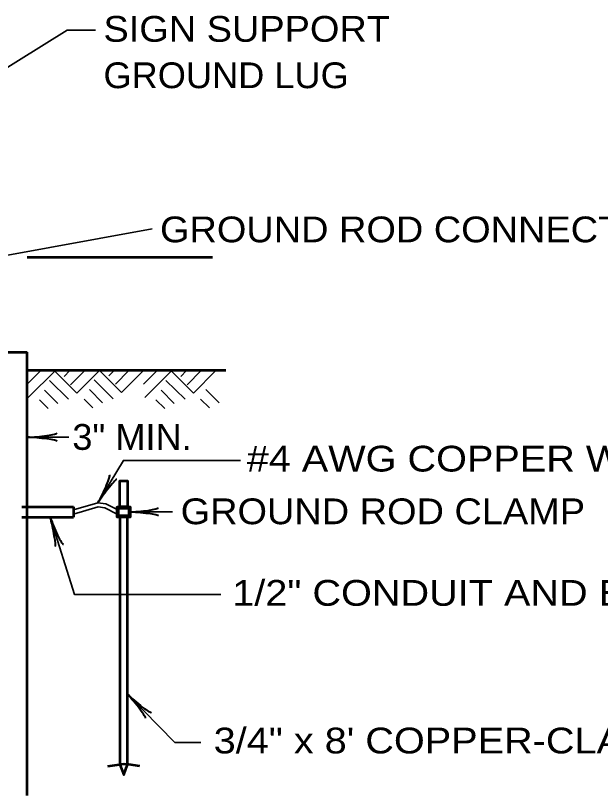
# Model space of a CAD drawing. Extents: x -68 to 612, y -58 to 382.
# Drawn here: x 208.3 to 265, y 135 to 210.6 of the extents above; entities that cross this region are included whole.
import ezdxf

# ---------------------------------------------------------------- set-up
doc = ezdxf.new("R2010")
doc.units = 0
doc.linetypes.add('LONG_DASHED', pattern=[7.5, 6, -1.5])
doc.layers.add('1', color=7, linetype='Continuous', lineweight=53)

msp = doc.modelspace()

# ---------------------------------------------------------------- linework, layer by layer
at = {"layer": '1', "lineweight": 35}
for p, q in [((195.016, 185.14), (221.485, 189.97)), ((210.686, 176.235), (209.366, 174.915)), ((212.106, 176.235), (209.486, 173.615)), ((212.006, 176.235), (214.206, 174.035)), ((213.526, 176.235), (212.966, 175.655)), ((214.966, 176.235), (213.586, 174.855)), ((216.386, 176.235), (214.206, 174.035)), ((216.386, 176.235), (218.526, 174.095)), ((217.806, 176.235), (217.286, 175.715)), ((219.246, 176.235), (217.926, 174.915)), ((220.666, 176.235), (218.526, 174.095)), ((221.986, 176.235), (220.666, 174.915)), ((223.406, 176.235), (220.786, 173.615)), ((223.306, 176.235), (225.506, 174.035)), ((224.826, 176.235), (224.266, 175.655)), ((226.266, 176.235), (224.886, 174.855)), ((227.686, 176.235), (225.506, 174.035)), ((211.526, 175.275), (213.386, 173.435)), ((215.866, 175.335), (217.706, 173.495)), ((222.826, 175.275), (224.686, 173.435)), ((211.066, 174.315), (212.346, 173.035)), ((215.406, 174.375), (216.686, 173.095)), ((222.366, 174.315), (223.646, 173.035)), ((226.706, 174.375), (227.986, 173.095)), ((210.566, 173.395), (211.426, 172.555)), ((214.886, 173.455), (215.746, 172.595)), ((221.866, 173.395), (222.726, 172.555)), ((226.186, 173.455), (227.046, 172.595)), ((209.407, 169.764), (213.407, 169.764)), ((219.241, 162.515), (223.463, 162.527))]:
    msp.add_line(p, q, dxfattribs=at)
at = {"layer": '1'}
for p, q in [((209.366, 187.207), (227.366, 187.207)), ((209.366, 135.025), (209.366, 178.015)), ((209.366, 176.275), (228.632, 176.275)), ((209.366, 163.015), (213.866, 163.015)), ((213.866, 163.015), (213.866, 162.015)), ((218.116, 163.002), (218.129, 163.015)), ((218.116, 162.988), (218.143, 163.015)), ((218.116, 162.974), (218.157, 163.015)), ((218.116, 162.96), (218.171, 163.015)), ((218.116, 162.946), (218.185, 163.015)), ((218.116, 162.932), (218.199, 163.015)), ((218.116, 162.917), (218.213, 163.015)), ((218.116, 162.903), (218.228, 163.015)), ((218.116, 162.889), (218.242, 163.015)), ((218.116, 162.875), (218.256, 163.015)), ((218.116, 162.861), (218.27, 163.015)), ((218.116, 162.847), (218.284, 163.015)), ((218.116, 162.833), (218.298, 163.015)), ((218.116, 162.819), (218.312, 163.015)), ((218.116, 162.804), (218.327, 163.015)), ((218.116, 162.79), (218.341, 163.015)), ((218.116, 162.776), (218.355, 163.015)), ((218.116, 162.762), (218.241, 162.887)), ((218.116, 162.748), (218.241, 162.873)), ((218.116, 162.734), (218.241, 162.859)), ((218.116, 162.719), (218.241, 162.844)), ((218.116, 162.705), (218.241, 162.83)), ((218.116, 162.691), (218.241, 162.816)), ((218.116, 162.677), (218.241, 162.802)), ((218.116, 162.663), (218.241, 162.788)), ((218.116, 162.649), (218.241, 162.774)), ((218.116, 162.635), (218.241, 162.76)), ((218.116, 162.62), (218.241, 162.745)), ((218.116, 162.606), (218.241, 162.731)), ((218.116, 162.592), (218.241, 162.717)), ((218.116, 162.578), (218.241, 162.703)), ((218.116, 162.564), (218.241, 162.689)), ((218.116, 162.55), (218.241, 162.675)), ((218.116, 162.536), (218.241, 162.661)), ((218.116, 162.522), (218.241, 162.647)), ((218.116, 162.507), (218.241, 162.632)), ((218.116, 162.493), (218.241, 162.618)), ((218.116, 162.479), (218.241, 162.604)), ((218.116, 162.465), (218.241, 162.59)), ((218.241, 162.89), (218.366, 162.89)), ((218.244, 162.89), (218.369, 163.015)), ((218.258, 162.89), (218.383, 163.015)), ((218.272, 162.89), (218.397, 163.015)), ((218.286, 162.89), (218.411, 163.015)), ((218.301, 162.89), (218.426, 163.015)), ((218.315, 162.89), (218.44, 163.015)), ((218.329, 162.89), (218.454, 163.015)), ((218.343, 162.89), (218.468, 163.015)), ((218.357, 162.89), (218.482, 163.015)), ((218.366, 163.015), (219.116, 163.015)), ((218.371, 162.89), (218.496, 163.015)), ((218.385, 162.89), (218.51, 163.015)), ((218.4, 162.89), (218.525, 163.015)), ((218.414, 162.89), (218.539, 163.015)), ((218.428, 162.89), (218.553, 163.015)), ((218.442, 162.89), (218.567, 163.015)), ((218.456, 162.89), (218.581, 163.015)), ((218.47, 162.89), (218.595, 163.015)), ((218.484, 162.89), (218.609, 163.015)), ((218.499, 162.89), (218.624, 163.015)), ((218.513, 162.89), (218.638, 163.015)), ((218.527, 162.89), (218.652, 163.015)), ((218.541, 162.89), (218.666, 163.015)), ((218.555, 162.89), (218.68, 163.015)), ((218.569, 162.89), (218.694, 163.015)), ((218.583, 162.89), (218.708, 163.015)), ((218.598, 162.89), (218.723, 163.015)), ((218.612, 162.89), (218.737, 163.015)), ((218.626, 162.89), (218.751, 163.015)), ((218.64, 162.89), (218.765, 163.015)), ((218.654, 162.89), (218.779, 163.015)), ((218.668, 162.89), (218.793, 163.015)), ((218.682, 162.89), (218.807, 163.015)), ((218.697, 162.89), (218.822, 163.015)), ((218.711, 162.89), (218.836, 163.015)), ((218.725, 162.89), (218.85, 163.015)), ((218.739, 162.89), (218.864, 163.015)), ((218.753, 162.89), (218.878, 163.015)), ((218.767, 162.89), (218.892, 163.015)), ((218.781, 162.89), (218.906, 163.015)), ((218.796, 162.89), (218.921, 163.015)), ((218.81, 162.89), (218.935, 163.015)), ((218.824, 162.89), (218.949, 163.015)), ((218.838, 162.89), (218.963, 163.015)), ((218.852, 162.89), (218.977, 163.015)), ((218.866, 162.89), (218.991, 163.015)), ((218.88, 162.89), (219.005, 163.015)), ((218.895, 162.89), (219.02, 163.015)), ((218.909, 162.89), (219.034, 163.015)), ((218.923, 162.89), (219.048, 163.015)), ((218.937, 162.89), (219.062, 163.015)), ((218.951, 162.89), (219.076, 163.015)), ((218.965, 162.89), (219.09, 163.015)), ((218.979, 162.89), (219.104, 163.015)), ((218.993, 162.89), (219.118, 163.015)), ((219.008, 162.89), (219.133, 163.015)), ((219.022, 162.89), (219.147, 163.015)), ((219.036, 162.89), (219.161, 163.015)), ((219.05, 162.89), (219.175, 163.015)), ((219.064, 162.89), (219.189, 163.015)), ((219.078, 162.89), (219.203, 163.015)), ((219.093, 162.89), (219.218, 163.015)), ((219.107, 162.89), (219.232, 163.015)), ((219.121, 162.89), (219.246, 163.015)), ((219.135, 162.89), (219.26, 163.015)), ((219.149, 162.89), (219.274, 163.015)), ((219.163, 162.89), (219.288, 163.015)), ((219.177, 162.89), (219.302, 163.015)), ((219.191, 162.89), (219.316, 163.015)), ((219.206, 162.89), (219.331, 163.015)), ((219.22, 162.89), (219.345, 163.015)), ((219.234, 162.89), (219.359, 163.015)), ((219.241, 162.883), (219.366, 163.008)), ((219.241, 162.869), (219.366, 162.994)), ((219.241, 162.855), (219.366, 162.98)), ((219.241, 162.84), (219.366, 162.965)), ((219.241, 162.826), (219.366, 162.951)), ((219.241, 162.812), (219.366, 162.937)), ((219.241, 162.798), (219.366, 162.923)), ((219.241, 162.784), (219.366, 162.909)), ((219.241, 162.77), (219.366, 162.895)), ((219.241, 162.755), (219.366, 162.88)), ((219.241, 162.741), (219.366, 162.866)), ((219.241, 162.727), (219.366, 162.852)), ((219.241, 162.713), (219.366, 162.838)), ((219.241, 162.699), (219.366, 162.824)), ((219.241, 162.685), (219.366, 162.81)), ((219.241, 162.671), (219.366, 162.796)), ((219.241, 162.657), (219.366, 162.782)), ((219.241, 162.642), (219.366, 162.767)), ((219.241, 162.628), (219.366, 162.753)), ((219.241, 162.614), (219.366, 162.739)), ((219.241, 162.6), (219.366, 162.725)), ((219.241, 162.586), (219.366, 162.711)), ((219.241, 162.572), (219.366, 162.697)), ((219.241, 162.558), (219.366, 162.683)), ((219.241, 162.543), (219.366, 162.668)), ((219.241, 162.529), (219.366, 162.654)), ((219.241, 162.515), (219.366, 162.64)), ((219.241, 162.501), (219.366, 162.626)), ((219.241, 162.487), (219.366, 162.612)), ((219.241, 162.473), (219.366, 162.598)), ((219.241, 162.459), (219.366, 162.584)), ((209.366, 162.015), (213.866, 162.015)), ((218.116, 162.451), (218.241, 162.576)), ((218.116, 162.437), (218.241, 162.562)), ((218.116, 162.422), (218.241, 162.547)), ((218.116, 162.408), (218.241, 162.533)), ((218.116, 162.394), (218.241, 162.519)), ((218.116, 162.38), (218.241, 162.505)), ((218.116, 162.366), (218.241, 162.491)), ((218.116, 162.352), (218.241, 162.477)), ((218.116, 162.338), (218.241, 162.463)), ((218.116, 162.323), (218.241, 162.448)), ((218.116, 162.309), (218.241, 162.434)), ((218.116, 162.295), (218.241, 162.42)), ((218.116, 162.281), (218.241, 162.406)), ((218.116, 162.267), (218.241, 162.392)), ((218.116, 162.253), (218.241, 162.378)), ((218.116, 162.239), (218.241, 162.364)), ((218.116, 162.225), (218.241, 162.35)), ((218.116, 162.21), (218.241, 162.335)), ((218.116, 162.196), (218.241, 162.321)), ((218.116, 162.182), (218.241, 162.307)), ((218.116, 162.168), (218.241, 162.293)), ((218.116, 162.154), (218.241, 162.279)), ((218.116, 162.14), (218.241, 162.265)), ((218.116, 162.125), (218.241, 162.25)), ((218.116, 162.111), (218.241, 162.236)), ((218.116, 162.097), (218.241, 162.222)), ((218.116, 162.083), (218.241, 162.208)), ((218.116, 162.069), (218.241, 162.194)), ((218.116, 162.055), (218.241, 162.18)), ((218.116, 162.041), (218.241, 162.166)), ((218.116, 162.026), (218.241, 162.151)), ((218.118, 162.015), (218.243, 162.14)), ((218.133, 162.015), (218.258, 162.14)), ((218.147, 162.015), (218.272, 162.14)), ((218.161, 162.015), (218.286, 162.14)), ((218.175, 162.015), (218.3, 162.14)), ((218.189, 162.015), (218.314, 162.14)), ((218.203, 162.015), (218.328, 162.14)), ((218.218, 162.015), (218.343, 162.14)), ((218.232, 162.015), (218.357, 162.14)), ((218.246, 162.015), (218.371, 162.14)), ((218.26, 162.015), (218.385, 162.14)), ((218.274, 162.015), (218.399, 162.14)), ((218.288, 162.015), (218.413, 162.14)), ((218.302, 162.015), (218.427, 162.14)), ((218.316, 162.015), (218.441, 162.14)), ((218.331, 162.015), (218.456, 162.14)), ((218.345, 162.015), (218.47, 162.14)), ((218.359, 162.015), (218.484, 162.14)), ((218.373, 162.015), (218.498, 162.14)), ((218.387, 162.015), (218.512, 162.14)), ((218.401, 162.015), (218.526, 162.14)), ((218.415, 162.015), (218.54, 162.14)), ((218.43, 162.015), (218.555, 162.14)), ((218.444, 162.015), (218.569, 162.14)), ((218.458, 162.015), (218.583, 162.14)), ((218.472, 162.015), (218.597, 162.14)), ((218.486, 162.015), (218.611, 162.14)), ((218.5, 162.015), (218.625, 162.14)), ((218.514, 162.015), (218.639, 162.14)), ((218.529, 162.015), (218.654, 162.14)), ((218.543, 162.015), (218.668, 162.14)), ((218.557, 162.015), (218.682, 162.14)), ((218.571, 162.015), (218.696, 162.14)), ((218.585, 162.015), (218.71, 162.14)), ((218.599, 162.015), (218.724, 162.14)), ((218.613, 162.015), (218.738, 162.14)), ((218.628, 162.015), (218.753, 162.14)), ((218.642, 162.015), (218.767, 162.14)), ((218.656, 162.015), (218.781, 162.14)), ((218.67, 162.015), (218.795, 162.14)), ((218.684, 162.015), (218.809, 162.14)), ((218.698, 162.015), (218.823, 162.14)), ((218.713, 162.015), (218.838, 162.14)), ((218.727, 162.015), (218.852, 162.14)), ((218.741, 162.015), (218.866, 162.14)), ((218.755, 162.015), (218.88, 162.14)), ((218.769, 162.015), (218.894, 162.14)), ((218.783, 162.015), (218.908, 162.14)), ((218.797, 162.015), (218.922, 162.14)), ((218.811, 162.015), (218.936, 162.14)), ((218.826, 162.015), (218.951, 162.14)), ((218.84, 162.015), (218.965, 162.14)), ((218.854, 162.015), (218.979, 162.14)), ((218.868, 162.015), (218.993, 162.14)), ((218.882, 162.015), (219.007, 162.14)), ((218.896, 162.015), (219.021, 162.14)), ((218.91, 162.015), (219.035, 162.14)), ((218.925, 162.015), (219.05, 162.14)), ((218.939, 162.015), (219.064, 162.14)), ((218.953, 162.015), (219.078, 162.14)), ((218.967, 162.015), (219.092, 162.14)), ((218.981, 162.015), (219.106, 162.14)), ((218.995, 162.015), (219.12, 162.14)), ((219.01, 162.015), (219.135, 162.14)), ((219.024, 162.015), (219.149, 162.14)), ((219.038, 162.015), (219.163, 162.14)), ((219.052, 162.015), (219.177, 162.14)), ((219.066, 162.015), (219.191, 162.14)), ((219.08, 162.015), (219.205, 162.14)), ((219.094, 162.015), (219.219, 162.14)), ((219.108, 162.015), (219.233, 162.14)), ((219.123, 162.015), (219.366, 162.258)), ((219.137, 162.015), (219.366, 162.244)), ((219.151, 162.015), (219.366, 162.23)), ((219.165, 162.015), (219.366, 162.216)), ((219.179, 162.015), (219.366, 162.202)), ((219.193, 162.015), (219.366, 162.188)), ((219.207, 162.015), (219.366, 162.173)), ((219.222, 162.015), (219.366, 162.159)), ((219.236, 162.015), (219.366, 162.145)), ((219.241, 162.444), (219.366, 162.569)), ((219.241, 162.43), (219.366, 162.555)), ((219.241, 162.416), (219.366, 162.541)), ((219.241, 162.402), (219.366, 162.527)), ((219.241, 162.388), (219.366, 162.513)), ((219.241, 162.374), (219.366, 162.499)), ((219.241, 162.36), (219.366, 162.485)), ((219.241, 162.345), (219.366, 162.47)), ((219.241, 162.331), (219.366, 162.456)), ((219.241, 162.317), (219.366, 162.442)), ((219.241, 162.303), (219.366, 162.428)), ((219.241, 162.289), (219.366, 162.414)), ((219.241, 162.275), (219.366, 162.4)), ((219.241, 162.261), (219.366, 162.386)), ((219.241, 162.246), (219.366, 162.371)), ((219.241, 162.232), (219.366, 162.357)), ((219.241, 162.218), (219.366, 162.343)), ((219.241, 162.204), (219.366, 162.329)), ((219.241, 162.19), (219.366, 162.315)), ((219.241, 162.176), (219.366, 162.301)), ((219.241, 162.162), (219.366, 162.287)), ((219.241, 162.147), (219.366, 162.272)), ((219.25, 162.015), (219.366, 162.131)), ((219.264, 162.015), (219.366, 162.117)), ((219.278, 162.015), (219.366, 162.103)), ((219.292, 162.015), (219.366, 162.089)), ((219.306, 162.015), (219.366, 162.074)), ((219.321, 162.015), (219.366, 162.06)), ((219.335, 162.015), (219.366, 162.046)), ((219.349, 162.015), (219.366, 162.032)), ((219.363, 162.015), (219.366, 162.018))]:
    msp.add_line(p, q, dxfattribs=at)
at = {"layer": '1', "linetype": 'LONG_DASHED'}
for p, q in [((201.366, 163.015), (209.366, 163.015)), ((201.366, 162.015), (209.366, 162.015))]:
    msp.add_line(p, q, dxfattribs=at)
at = {"layer": '1', "lineweight": 35}
for points in [[(201.023, 201.626), (213.267, 209.222), (216.001, 209.222)], [(216.237, 163.409), (218.709, 167.507), (230.068, 167.507)], [(213.866, 162.723), (216.237, 163.409), (217.018, 163.297), (218.116, 162.739), (218.116, 162.29)], [(218.116, 162.29), (216.895, 162.911), (216.265, 163.001), (213.866, 162.307), (213.866, 162.723)], [(211.616, 162.015), (213.952, 154.515), (228.166, 154.515)], [(219.116, 144.835), (223.706, 140.164), (226.207, 140.164)]]:
    msp.add_lwpolyline(points, dxfattribs=at)
at = {"layer": '1'}
for points in [[(178.866, 135.025), (178.866, 178.015), (209.366, 178.015)], [(217.21, 137.875), (218.327, 138.007), (218.771, 138.079), (219.203, 138.043), (220.284, 137.899)]]:
    msp.add_lwpolyline(points, dxfattribs=at)
for points in [[(218.366, 163.015), (218.366, 165.515), (219.116, 165.515), (219.116, 163.015)], [(218.116, 163.015), (218.366, 163.015), (219.116, 163.015), (219.366, 163.015), (219.366, 162.015), (219.116, 162.015), (218.366, 162.015), (218.116, 162.015), (218.116, 162.29), (218.116, 162.739)], [(218.241, 162.89), (219.116, 162.89), (219.241, 162.89), (219.241, 162.14), (219.116, 162.14), (218.241, 162.14), (218.241, 162.29), (218.241, 162.739)], [(219.116, 138.015), (219.116, 162.015), (218.366, 162.015), (218.366, 138.015), (218.741, 137.015)]]:
    msp.add_lwpolyline(points, close=True, dxfattribs=at)
at = {"layer": '1', "lineweight": 40}
for centre, major_axis, ratio, start_param, end_param in [((210.498, 170.041), (-1.786, -0.156), 0.122415, 0.896353, 3.141593), ((210.498, 170.041), (-1.786, -0.156), 0.122415, 0.896353, 3.141593), ((210.528, 169.553), (-1.756, 0.176), 0.07063, 3.140715, 5.41811), ((210.528, 169.553), (-1.756, 0.176), 0.07063, 3.140715, 5.41811), ((216.564, 164.486), (-0.789, -1.61), 0.122415, 0.896353, 3.141593), ((216.564, 164.486), (-0.789, -1.61), 0.122415, 0.896353, 3.141593), ((216.997, 164.259), (1.058, 1.413), 0.07063, 6.282307, 8.559703), ((216.997, 164.259), (1.058, 1.413), 0.07063, 6.282307, 8.559703), ((220.332, 162.794), (-1.785, -0.161), 0.122415, 0.896353, 3.141593), ((211.747, 160.882), (0.355, -1.729), 0.07063, 6.282307, 8.559703), ((212.204, 161.055), (-0.68, 1.658), 0.122415, 0.896353, 3.141593), ((220.362, 162.306), (-1.757, 0.171), 0.07063, 3.140715, 5.41811), ((219.75, 143.888), (-1.106, 1.376), 0.07063, 3.140715, 5.41811), ((219.75, 143.888), (-1.106, 1.376), 0.07063, 3.140715, 5.41811), ((220.078, 144.251), (-1.363, 1.164), 0.122415, 0.896353, 3.141593), ((220.078, 144.251), (-1.363, 1.164), 0.122415, 0.896353, 3.141593)]:
    msp.add_ellipse(centre, major_axis=major_axis, ratio=ratio, start_param=start_param, end_param=end_param, dxfattribs=at)

# ---------------------------------------------------------------- texts
at = {"layer": '1'}
for s, width, p in [('SIGN SUPPORT', 1.1, (216.775, 208.108)), ('GROUND LUG', 1.05, (216.775, 203.608)), ('GROUND ROD CONNECTOR', 1.1, (222.26, 188.66)), ('3" MIN.', 1.05, (213.752, 168.534)), ('#4 AWG COPPER WIRE', 1.15, (230.669, 166.431)), ('GROUND ROD CLAMP', 1.1, (224.262, 161.324)), ('1/2" CONDUIT AND END BUSHING', 1.15, (229.267, 153.414)), ('3/4" x 8\' COPPER-CLAD GROUND ROD', 1.15, (227.466, 139.095))]:
    msp.add_text(s, height=2.5, dxfattribs=dict(at, width=width)).set_placement(p)

doc.saveas('drawing.dxf')
